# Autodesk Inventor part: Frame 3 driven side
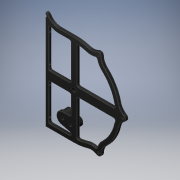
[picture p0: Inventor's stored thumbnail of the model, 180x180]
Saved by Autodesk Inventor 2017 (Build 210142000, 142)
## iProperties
Created: 2016-07
Part Number: Frame 3 driven side
Material: Generic
Document SubType Name: Modeling
Designer: Stan
Density: 1 g/cm^3
Appearance: Glossy - Black
Author: Stan
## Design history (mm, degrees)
sketch "Sketch1"
  geometry: L1 (-33.07, 98.425)-(0, 98.425); L2 (-33.07, 88.9)-(-9.525, 88.9); L3 (-60.566, -98.425)-(0, -98.425); L4 (-51.041, -9.525)-(-9.525, -9.525); L5 (9.525, -9.525)-(85.613, -9.525); L6 (-51.041, 9.525)-(-9.525, 9.525); L7 (9.525, 9.525)-(85.613, 9.525); L8 (-51.041, -88.9)-(-9.525, -88.9); L9 (-6.35, -12.7)-(-6.35, -49.415); L10 (-6.35, -85.349)-(-6.35, -85.725); L11 (6.35, -12.7)-(6.35, -85.194); L12 (-6.35, 12.7)-(-6.35, 85.725); L13 (6.35, 12.7)-(6.35, 85.194); L14 (-60.566, 114.3)-(-60.566, 110.49); L15 (-60.566, 105.41)-(-60.566, -98.425); L16 (-54.216, 90.23)-(-54.216, 12.7); L17 (-54.216, -12.7)-(-54.216, -85.725); L18 (-24.745, -52.59)-(-8.963, -52.59); L19 (-27.874, -77.599)-(-11.125, -81.856); C1 r 2.54 at (104.775, 0); C2 r 2.54 at (52.387, -90.738); C3 r 2.54 at (52.388, 90.738); C4 r 3.175 at (-24.745, -65.29); C5 r 3.175 at (-7.996, -69.548); A1 r 3.175 centre (-9.525, 85.725) between (-6.35, 85.725) and (-9.525, 88.9); A2 r 3.175 centre (-51.041, -12.7) between (-51.041, -9.525) and (-54.216, -12.7); A3 r 3.175 centre (-9.525, -12.7) between (-6.35, -12.7) and (-9.525, -9.525); A4 r 3.175 centre (-9.525, 12.7) between (-9.525, 9.525) and (-6.35, 12.7); A5 r 3.175 centre (9.525, 12.7) between (6.35, 12.7) and (9.525, 9.525); A6 r 98.425 centre (0, 0) between (0, -98.425) and (29.099, -94.025); A7 r 98.425 centre (0, 0) between (66.878, -72.213) and (95.978, -21.812); A8 r 98.425 centre (0, 0) between (95.978, 21.812) and (66.878, 72.213); A9 r 98.425 centre (0, 0) between (29.099, 94.025) and (0, 98.425); A10 r 88.9 centre (0, 0) between (9.878, -88.35) and (26.283, -84.926); A11 r 88.9 centre (0, 0) between (60.406, -65.225) and (86.69, -19.701); A12 r 3.175 centre (9.525, -85.194) between (6.35, -85.194) and (9.878, -88.35); A13 r 88.9 centre (0, 0) between (86.69, 19.701) and (60.406, 65.225); A14 r 88.9 centre (0, 0) between (26.283, 84.926) and (9.878, 88.35); A15 r 3.175 centre (9.525, 85.194) between (9.878, 88.35) and (6.35, 85.194); A16 r 6.35 centre (104.775, 0) between (107.969, -5.488) and (107.969, 5.488); A17 r 25.4 centre (120.746, 27.441) between (95.978, 21.812) and (107.969, 5.488); A18 r 34.925 centre (120.746, 27.441) between (86.69, 19.701) and (88.541, 13.928); A19 r 3.175 centre (85.613, 12.7) between (85.613, 9.525) and (88.541, 13.928); A20 r 25.4 centre (120.746, -27.441) between (107.969, -5.488) and (95.978, -21.812); A21 r 34.925 centre (120.746, -27.441) between (88.541, -13.928) and (86.69, -19.701); A22 r 3.175 centre (85.613, -12.7) between (88.541, -13.928) and (85.613, -9.525); A23 r 6.35 centre (52.387, -90.738) between (49.232, -96.248) and (58.737, -90.76); A24 r 25.4 centre (84.137, -90.849) between (66.878, -72.213) and (58.737, -90.76); A25 r 34.925 centre (84.137, -90.849) between (60.406, -65.225) and (50.239, -82.443); A26 r 25.4 centre (36.609, -118.29) between (49.232, -96.248) and (29.099, -94.025); A27 r 34.925 centre (36.609, -118.29) between (46.278, -84.73) and (26.283, -84.926); A28 r 3.175 centre (47.157, -81.679) between (46.278, -84.73) and (50.239, -82.443); A29 r 6.35 centre (52.388, 90.738) between (58.737, 90.76) and (49.232, 96.248); A30 r 25.4 centre (36.609, 118.29) between (29.099, 94.025) and (49.232, 96.248); A31 r 34.925 centre (36.609, 118.29) between (26.283, 84.926) and (46.278, 84.73); A32 r 25.4 centre (84.137, 90.849) between (58.737, 90.76) and (66.878, 72.213); A33 r 34.925 centre (84.137, 90.849) between (50.239, 82.443) and (60.406, 65.225); A34 r 3.175 centre (47.157, 81.679) between (50.239, 82.443) and (46.278, 84.73); A35 r 6.35 centre (-60.566, 107.95) between (-55.067, 111.125) and (-60.566, 114.3); A36 r 25.4 centre (-33.07, 123.825) between (-55.067, 111.125) and (-33.07, 98.425); A37 r 34.925 centre (-33.07, 123.825) between (-49.544, 93.029) and (-33.07, 88.9); A38 r 3.175 centre (-51.041, 90.23) between (-49.544, 93.029) and (-54.216, 90.23); A39 r 2.54 centre (-60.566, 107.95) between (-60.566, 105.41) and (-60.566, 110.49); A40 r 3.175 centre (-9.525, -85.725) between (-9.525, -88.9) and (-6.35, -85.725); A41 r 3.175 centre (9.525, -12.7) between (9.525, -9.525) and (6.35, -12.7); A42 r 3.175 centre (-51.041, 12.7) between (-54.216, 12.7) and (-51.041, 9.525); A43 r 3.175 centre (-51.041, -85.725) between (-54.216, -85.725) and (-51.041, -88.9); A44 r 12.7 centre (-24.745, -65.29) between (-24.745, -52.59) and (-27.874, -77.599); A45 r 12.7 centre (-7.996, -69.548) between (-11.125, -81.856) and (-9.219, -82.189); A46 r 3.175 centre (-9.525, -85.349) between (-6.35, -85.349) and (-9.219, -82.189); 2 further points; 1 other entity
  constraints: 92 point on circle, 51 centre point, 38 end point, 4 other
  dimensions: "d7" = 5.08 diameter of C3; "d8" = 5.08 diameter of C1; "d9" = 5.08 diameter of C2; "d10" = 6.35 diameter of C4; "d11" = 6.35 diameter of C5
extrude "Extrusion1" new body sketch "Sketch1" distance "d1" = 6.35; taper "d2" = 0 deg
sketch "Sketch2"
  geometry: C1 r 4.763 at (0, 0); 1 further point
  constraints: 1 centre point, 1 coincident
  dimensions: "d3" = 9.525 diameter of C1
extrude "Extrusion2" cut sketch "Sketch2" distance "d4" = 6.35; taper "d5" = 0 deg
fillet "Fillet1" dims "d6" = 0.79375
sketch "Sketch3"
  geometry: L1 (0, 0)-(0, 203.835) reference; C1 r 1.587 at (3.175, 79.375); C2 r 1.587 at (3.175, 19.05); C3 r 1.587 at (3.175, 117.475); C4 r 1.587 at (3.175, 177.8); 3 further points
  constraints: 4 centre point
  dimensions: "d12" = 9.525 vertical distance of C1.centre point (5.556, 88.9); "d13" = 9.525 vertical distance of C3.centre point (5.556, 107.95); "d14" = 60.325 distance of C4.centre C3.centre; "d15" = 60.325 distance of C2.centre C1.centre; "d16" = 3.175 distance from line of L1 C1.centre; "d17" = 3.175 distance from line of L1 C2.centre; "d18" = 3.175 distance from line of L1 C3.centre; "d19" = 3.175 distance from line of L1 C4.centre; "d20" = 3.175 diameter of C4; "d21" = 3.175 diameter of C3; "d22" = 3.175 diameter of C1; "d23" = 3.175 diameter of C2
extrude "Extrusion3" cut sketch "Sketch3" distance "d24" = 6.35; taper "d25" = 0 deg
sketch "Sketch5"
  geometry: C1 r 3.175 at (24.745, -65.29) reference; C2 r 3.175 at (7.996, -69.548) reference; C3 r 3.175 at (7.996, -69.548); C4 r 3.175 at (24.745, -65.29); A1 r 11.113 centre (24.745, -65.29) between (16.836, -73.096) and (14.069, -62.209); A2 r 9.525 centre (7.996, -69.548) between (14.069, -62.209) and (16.836, -73.096); 1 further point
  constraints: 4 centre point, 4 coincident, 4 point on circle, 2 concentric
  dimensions: "d31" = 22.225 diameter of A1; "d32" = 19.05 diameter of A2
extrude "Extrusion5" join sketch "Sketch5" distance "d33" = 12.7; taper "d34" = 0 deg
fillet "Fillet3" dims "d35" = 0.79375
body "Solid1"
